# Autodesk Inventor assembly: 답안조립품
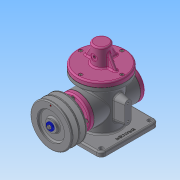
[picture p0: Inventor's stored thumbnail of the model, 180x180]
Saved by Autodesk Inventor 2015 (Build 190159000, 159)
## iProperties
Created: 2020-02
Part Number: 답안조립품
Document SubType Name: Assembly
Designer: user
Author: user
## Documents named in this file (21)
- C:\Users\user\Desktop\600206V1008\답안조립품.iam
- C:\Users\user\Desktop\600206V1008\본체.ipt
- C:\Users\user\Desktop\600206V1008\베어링 17 x 40 x 12.ipt
- C:\Users\user\Desktop\600206V1008\개스킷 A.ipt
- C:\Users\user\Desktop\600206V1008\뒤커버.ipt
- C:\Users\user\Desktop\600206V1008\육각 소켓 머리 볼트 M4 x 10.ipt
- C:\Users\user\Desktop\600206V1008\편심축.ipt
- C:\Users\user\Desktop\600206V1008\키 4 x 4 x 25.ipt
- C:\Users\user\Desktop\600206V1008\앞커버.ipt
- C:\Users\user\Desktop\600206V1008\오일 실 17 30 8.ipt
- C:\Users\user\Desktop\600206V1008\V-벨트풀리.ipt
- C:\Users\user\Desktop\600206V1008\와셔 4x16.ipt
- C:\Users\user\Desktop\600206V1008\볼트 M4 x 10.ipt
- C:\Users\user\Desktop\600206V1008\링크.ipt
- C:\Users\user\Desktop\600206V1008\클레비스 핀 6 x 22.ipt
- 클레비스 핀 6 x 22.ipt
- C:\Users\user\Desktop\600206V1008\E-링.ipt
- C:\Users\user\Desktop\600206V1008\슬라이더.ipt
- C:\Users\user\Desktop\600206V1008\가변스프링.ipt
- C:\Users\user\Desktop\600206V1008\개스킷 B.ipt
- C:\Users\user\Desktop\600206V1008\덮개.ipt
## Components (6 placed, 5 different names)
1. 개스킷 A:1
2. 개스킷 A:2
3. V-벨트풀리:1
4. E-링:1
5. 가변스프링:1
6. 개스킷 B:1
